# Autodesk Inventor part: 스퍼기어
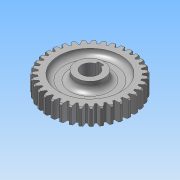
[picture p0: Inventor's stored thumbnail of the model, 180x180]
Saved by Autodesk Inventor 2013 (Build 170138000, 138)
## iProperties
Created: 2013-08
Part Number: 스퍼기어
Material: 강
Document SubType Name: Modeling
Designer: 한국산업디자인학원
Categories: <?xml version="1.0" encoding="UTF-16"?> <MemberInstance><Categories><FamilyTemplate><FamilyTemplateParameter ValueType="xs:double" Id="1" ObjectReferenceKey="da
Density: 1 g/cm^3
CustomPartVersion: 1
Author: 한국산업디자인학원
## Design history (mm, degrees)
sketch "Sketch1"
  geometry: C1 r 37 at (0, 0)
  constraints: 1 centre point
  dimensions: "d0" = 74 diameter of C1 (= da_da)
extrude "Extrusion1" new body sketch "Sketch1" distance "d1" = 15 (= da_b); taper "d2" = 0 deg
chamfer "모따기1" distance "d49" = 1; stored, may be unused: second distance "d50" = 2, angle "d51" = 45 deg
workplane "Work Plane2"
feature "피치 지름" dims "d4" = 10, "d5" = 0
workplane "Work Plane8"
workplane "Work Plane9"
feature "스퍼 기어" dims "da_b" = 15, "da_d" = 70, "da_aw" = 70, "da_da" = 74, "da_df" = 65, "da_dw" = 70, angle "da_beta" = 0 deg, "da_lefttooth" = 0, "da_righttooth" = 0
node "작업 평면11"
sketch "스케치4"
  geometry: C1 r 12.5 at (0, 0); 1 further point
  constraints: 1 centre point, 1 coincident
  dimensions: "d53" = 25 diameter of C1
extrude "돌출2" join sketch "스케치4" distance "d55" = 31; taper "d56" = 0 deg
sketch "스케치5"
  geometry: C1 r 12.5 at (0, 0) reference; C2 r 27.5 at (0, 0); A1 r 36 centre (0, 0) between (-5.215, 35.62) and (-7.633, 35.181) reference
  constraints: 1 centre point, 1 coincident
  dimensions: "d57" = 55 diameter of C2
extrude "돌출3" cut sketch "스케치5" distance "d59" = 5; taper "d60" = 0 deg
sketch "스케치6"
  geometry: C1 r 12.5 at (0, 0) reference; C2 r 27.5 at (0, 0) reference
extrude "돌출4" cut sketch "스케치6" distance "d61" = 5; taper "d62" = 0 deg
sketch "스케치7"
  geometry: L1 (-2.5, 7.071)-(-2.5, 9.8); L2 (-2.5, 9.8)-(2.5, 9.8); L3 (2.5, 9.8)-(2.5, 7.071); C1 r 12.5 at (0, 0) reference; A1 r 7.5 centre (0, 0) between (-2.5, 7.071) and (2.5, 7.071)
  constraints: 6 end point, 2 parallel, 2 point on circle, 1 centre point, 1 coincident, 1 perpendicular, 1 vertical
  dimensions: "d63" = 15 diameter of A1; "d65" = 5 distance of L1.end L2.end; "d66" = 17.3 dimension on A1 L2
extrude "돌출5" cut sketch "스케치7" stored distance "d67" = 5; taper "d68" = 0 deg
fillet "모깎기1" dims "d69" = 5
body "Solid1"
sketch "Sketch2"
  geometry: C1 r 37 at (0, 0) reference; C2 r 35 at (0, 0)
  constraints: 1 centre point, 1 coincident
  dimensions: "d3" = 70 diameter of C2 (= da_dw)
body "Srf1"
other parameters: "d17" = 0, "d34" = 0.8976 (computed from da_z), "d39" = 0, "d41" = 0, "d47" = 0, "d48" = 0, "d52" = 3
